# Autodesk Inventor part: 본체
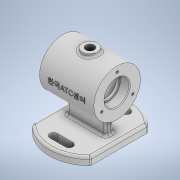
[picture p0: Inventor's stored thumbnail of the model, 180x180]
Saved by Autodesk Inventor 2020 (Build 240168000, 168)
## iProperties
Created: 2021-09
Part Number: 본체
Material: Generic
Document SubType Name: Modeling
Designer: Administrator
Density: 1 g/cm^3
Appearance: Default
Author: Administrator
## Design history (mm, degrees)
sketch "스케치1"
  geometry: L1 (37.5, 91.616)-(-37.5, 91.616); L2 (-37.5, 91.616)-(-37.5, -91.616); L3 (-37.5, -91.616)-(37.5, -91.616); L4 (37.5, -91.616)-(37.5, 91.616); L5 (37.5, 91.616)-(-37.5, -91.616); L6 (-37.5, 91.616)-(37.5, -91.616); C1 r 52.5 at (0, 0); 5 further points
  constraints: 12 end point, 2 midpoint, 2 parallel, 1 centre point, 1 coincident, 1 horizontal, 1 perpendicular
  dimensions: "d0" = 105 diameter of C1; "d1" = 75 distance of L1.start L1.end
extrude "돌출1" new body sketch "스케치1" distance "d2" = 10; taper "d3" = 0 deg
sketch "스케치2"
  geometry: L1 (0, 0)-(0, 62); L2 (0, 62)-(35, 62); L3 (0, 62)-(-35, 62); L4 (-35, 62)-(-35, 92); L5 (-35, 92)-(35, 92); L6 (35, 92)-(35, 62)
  constraints: 12 end point, 2 perpendicular, 1 horizontal, 1 point on line, 1 vertical
  dimensions: "d9" = 35 distance of L1.end L2.end; "d10" = 35 distance of L1.end L3.end; "d11" = 30 distance of L3.end L4.end; "d12" = 70 distance of L4.end L5.end
revolve "회전1" sketch "스케치2" stored, may be unused: angle "d13" = 90 deg
sketch "스케치3"
  geometry: L1 (0, 0)-(25, 0); L2 (25, 0)-(25, 62); L3 (25, 62)-(0, 62); L4 (0, 62)-(0, 0); L5 (0, 0)-(-25, 0); L6 (-25, 0)-(-25, 62); L7 (-25, 62)-(0, 62); L8 (0, 62)-(0, 0); 1 further point
  constraints: 16 end point, 4 parallel, 2 horizontal, 2 perpendicular
  dimensions: "d14" = 25 distance of L3.end L2.end; "d15" = 62 distance of L2.end L1.end; "d16" = 25 distance of L6.end L7.end
extrude "돌출2" join sketch "스케치3" stored distance "d17" = 10; taper "d18" = 0 deg
sketch "스케치4" dims "d21" = 10, "d22" = 10, "d23" = 10, "d24" = 10
  geometry: L1 (-10, -37)-(-10, 37); L2 (-10, 37)-(10, 37); L3 (10, 37)-(10, -37); L4 (10, -37)-(-10, -37); L5 (-10, -37)-(10, 37); L6 (-10, 37)-(10, -37); L7 (-10, -42)-(10, -42); L8 (10, -42)-(10, -32); L9 (10, -32)-(-10, -32); L10 (-10, -32)-(-10, -42); L11 (10, 32)-(-10, 32); L12 (-10, 32)-(-10, 42); L13 (-10, 42)-(10, 42); L14 (10, 42)-(10, 32); 9 further points
  constraints: 28 end point, 6 parallel, 4 coincident, 3 perpendicular, 2 horizontal, 2 midpoint, 2 point on line, 1 vertical, 12 other
  dimensions: "d19" = 74 distance of L1.start L1.end; "d20" = 20 distance of L1.end L2.end
extrude "돌출3" cut sketch "스케치4" distance "d25" = 10; taper "d26" = 0 deg
node "작업 평면2"
sketch "스케치6"
  geometry: C1 r 10 at (0, 0); 1 further point
  constraints: 1 centre point, 1 coincident
  dimensions: "d28" = 20 diameter of C1
extrude "돌출4" join sketch "스케치6" distance "d29" = 10; taper "d30" = 0 deg
sketch "스케치7"
  geometry: L1 (-35, 32)-(-35, 92) reference; L2 (-35, 62)-(35, 62); L3 (35, 32)-(35, 92) reference; L4 (-35, 62)-(-23, 62); L5 (-23, 62)-(-23, 78); L6 (-23, 78)-(-35, 78); L7 (-35, 78)-(-35, 62); L8 (-20, 87)-(-20, 37); L9 (-20, 37)-(20, 37); L10 (20, 37)-(20, 87); L11 (20, 87)-(-20, 87); L12 (-20, 87)-(20, 37); L13 (-20, 37)-(20, 87); L14 (35, 62)-(23, 62); L15 (23, 62)-(23, 78); L16 (23, 78)-(35, 78); L17 (35, 78)-(35, 62); L18 (23, 62)-(20, 62); L19 (20, 62)-(20, 76); L20 (20, 76)-(23, 76); L21 (23, 76)-(23, 62); L22 (-23, 62)-(-20, 62); L23 (-20, 62)-(-20, 76); L24 (-20, 76)-(-23, 76); L25 (-23, 76)-(-23, 62); 6 further points
  constraints: 46 end point, 10 parallel, 6 perpendicular, 5 midpoint, 4 horizontal, 2 point on line
  dimensions: "d31" = 12 distance of L6.end L5.end; "d32" = 16 distance of L5.end L4.end; "d33" = 50 distance of L8.start L8.end; "d34" = 40 distance of L9.end L8.end; "d35" = 12 distance of L15.end L16.end; "d36" = 16 distance of L14.end L15.end; "d37" = 14 distance of L18.end L19.end; "d38" = 14 distance of L23.end L22.end
revolve "회전2" sketch "스케치7" stored, may be unused: angle "d39" = 90 deg
sketch "스케치8"
  geometry: C1 r 10 at (0, 0) reference; 2 further points
  constraints: 1 coincident
hole "구멍1" sketch "스케치8" at (0, 0) diameter "d40" = 10.917; stored, may be unused: countersink angle "d44" = 90 deg, drill point angle "d46" = 118 deg; dims "d41" = 24, "d42" = 4, "d43" = 2, "d45" = 29.1
sketch "스케치9" dims "d47" = 46
  geometry: C1 r 30 at (0, 0) reference; 3 further points
  constraints: 1 coincident, 1 vertical alignment, 2 other
hole "구멍2" sketch "스케치9" at (0, 23) diameter "d48" = 3.242; stored, may be unused: countersink angle "d52" = 90 deg, drill point angle "d54" = 118 deg; dims "d49" = 8, "d50" = 4, "d51" = 2, "d53" = 10
node "작업 평면3"
sketch "스케치10"
  geometry: L1 (-35, 30)-(35, 30) reference; L2 (-35, -30)-(-35, 30) reference; 3 further points
  constraints: 1 coincident, 1 other
  dimensions: "d58" = 30 distance from line of L1 point (0, 0); "d59" = 35 distance from line of point (0, 0) L2
feature "엠보싱1" sketch "스케치10" dims "d0" = 105, "d1" = 75, "d14" = 25, "d15" = 62, "d60" = 0.5, "d61" = 0
fillet "모깎기1" dims "d62" = 3
fillet "모깎기2" dims "d63" = 3
fillet "모깎기3" dims "d64" = 3
fillet "모깎기4" dims "d65" = 3
fillet "모깎기5" dims "d66" = 0.3
fillet "모깎기6" dims "d67" = 3
fillet "모깎기7" dims "d68" = 3
chamfer "모따기1" distance "d69" = 1; stored, may be unused: second distance "d70" = 2, angle "d71" = 45 deg
node "솔리드1"
pattern_circular "원형 패턴1" dims angle "d56" = 360 deg
mirror "미러1"
feature "A9D066F2-1C7D-4E18-AEED-F7BC21143FA4" dims "d48" = 3.242, "d49" = 8, "d50" = 4, "d51" = 2, "d52" = 90 deg, "d53" = 10, "d54" = 118 deg
other parameters: "d27" = 95
